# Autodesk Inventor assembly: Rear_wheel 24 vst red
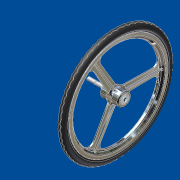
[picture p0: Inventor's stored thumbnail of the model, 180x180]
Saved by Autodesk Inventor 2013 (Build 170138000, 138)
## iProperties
Shininess: 20.0
Length Units: 11269
Angle Units: 11279
Time Units: 11290
Mass Units: 11283
Length Display Precision: 3
Angle Display Precision: 2
Created: 2001-04
Part Number: Rear_wheel 24 vst red
Document SubType Name: Baugruppe
Designer: dl
Density: 0.0
Volumn: 0.0
Area: 0.0
PropertySet Name: Model Information
Control State: 0
Master: False
Checked Out: False
Author: dl
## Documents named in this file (9)
- C:\Webworld\Webworld2014\ATC2013\Assemblies\ATC-Baby Carriage\2-REAR WHEEL\Rear_wheel 24 vst red.iam
- C:\Webworld\Webworld2014\ATC2013\Assemblies\ATC-Baby Carriage\2-REAR WHEEL\DIN 625 T1 - 6201 - 12 x 32 x 10.ipt
- C:\Webworld\Webworld2014\ATC2013\Assemblies\ATC-Baby Carriage\2-REAR WHEEL\Circlip - DIN 471 - 15 X 1.ipt
- C:\Webworld\Webworld2014\ATC2013\Assemblies\ATC-Baby Carriage\2-REAR WHEEL\Rim_carbon.ipt
- C:\Webworld\Webworld2014\ATC2013\Assemblies\ATC-Baby Carriage\2-REAR WHEEL\Bearing_shell.ipt
- C:\Webworld\Webworld2014\ATC2013\Assemblies\ATC-Baby Carriage\2-REAR WHEEL\Tyre.ipt
- C:\Webworld\Webworld2014\ATC2013\Assemblies\ATC-Baby Carriage\2-REAR WHEEL\Rear_wheel_axis_24.ipt
- C:\Webworld\Webworld2014\ATC2013\Assemblies\ATC-Baby Carriage\2-REAR WHEEL\Countersunk_bolt_Rear_wheel_axis.ipt
- C:\Webworld\Webworld2014\ATC2013\Assemblies\ATC-Baby Carriage\2-REAR WHEEL\O-Ring 15x2.ipt
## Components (9 placed, 8 different names)
1. Rear_wheel_axis_24:1 — Mate:1, Insert:1
2. Tyre:1
3. Countersunk_bolt_Rear_wheel_axis:1 — Insert:2
4. O-Ring 15x2:1 — Mate:1, Mate:2
5. Circlip - DIN 471 - 15 X 1:1 — Mate:2, Insert:1
6. DIN 625 T1 - 6201 - 12 x 32 x 10:1
7. DIN 625 T1 - 6201 - 12 x 32 x 10:2 — Insert:2
8. Rim_carbon:1 — Flush:1, Insert:3
9. Bearing_shell:1 — Flush:1, Insert:3
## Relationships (6: Insert 3, Mate 2, Flush 1)
- Mate:1: Rear_wheel_axis_24:1 ↔ O-Ring 15x2:1
- Mate:2: O-Ring 15x2:1 ↔ Circlip - DIN 471 - 15 X 1:1
- Insert:1: Rear_wheel_axis_24:1 ↔ Circlip - DIN 471 - 15 X 1:1
- Insert:2: Countersunk_bolt_Rear_wheel_axis:1 ↔ DIN 625 T1 - 6201 - 12 x 32 x 10:2
- Flush:1: Rim_carbon:1 ↔ Bearing_shell:1
- Insert:3: Rim_carbon:1 ↔ Bearing_shell:1
